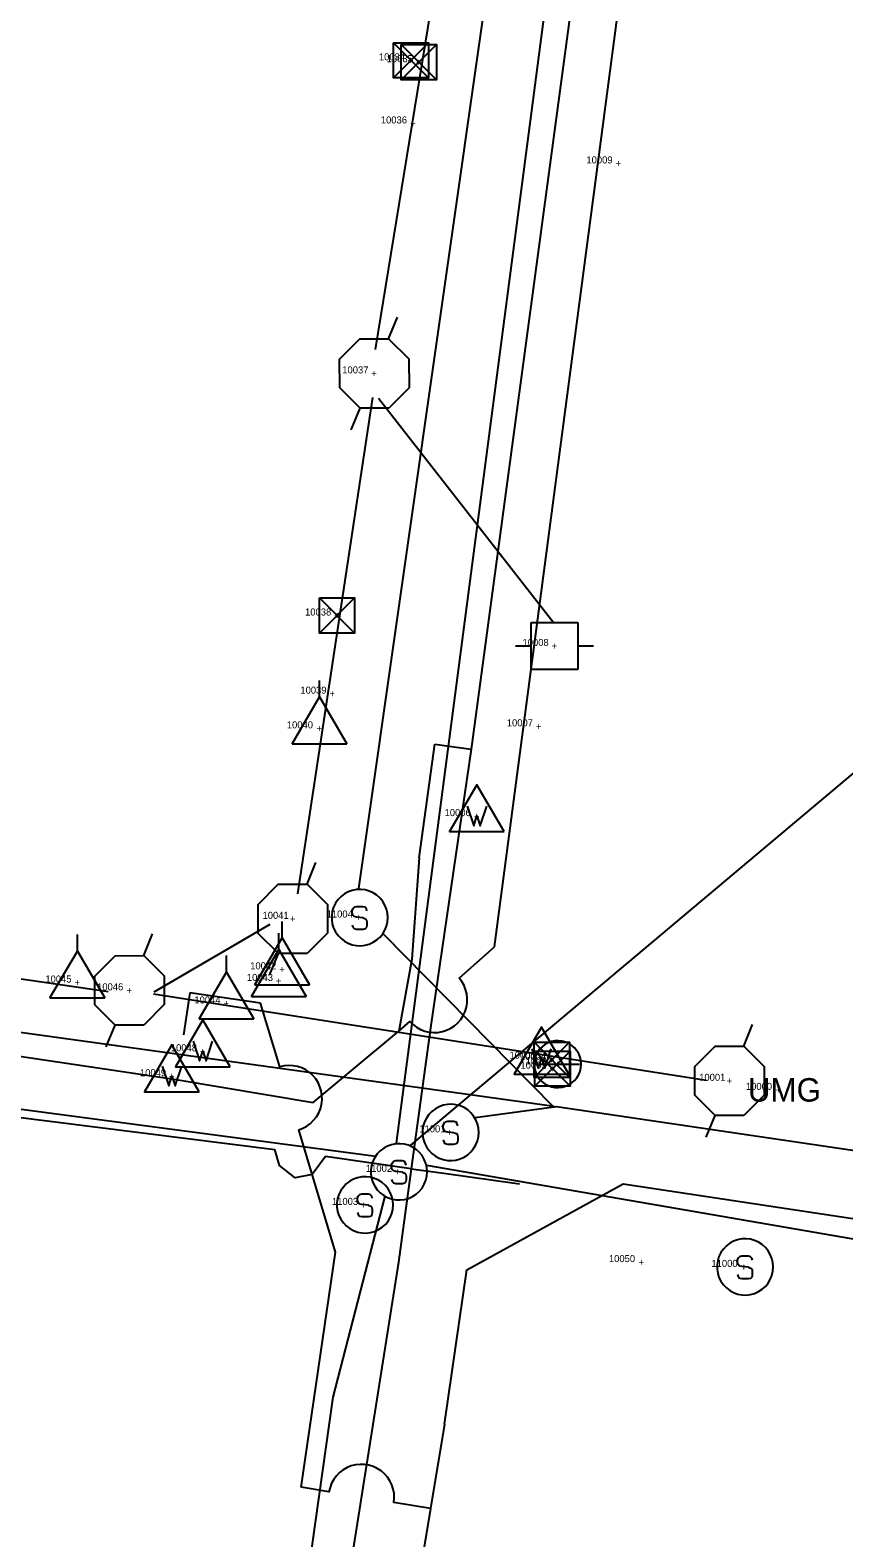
# Model space of a CAD drawing. Extents: x 1795905 to 1799611, y 243768 to 252016.
# Drawn here: x 1797403.8 to 1797577.2, y 244338.3 to 244659.6 of the extents above; entities that cross this region are included whole.
import ezdxf

# ---------------------------------------------------------------- set-up
doc = ezdxf.new("R2010")
doc.units = 0
for name, color, linetype in [('Level 50', 7, 'Continuous'), ('LS-SURVEY POINT', 7, 'Continuous'), ('OHUT', 7, 'Continuous'), ('OHUTTXT', 7, 'Continuous'), ('UGUT', 7, 'Continuous'), ('UGUTTXT', 7, 'Continuous')]:
    doc.layers.add(name, color=color, linetype=linetype)

msp = doc.modelspace()

# ---------------------------------------------------------------- linework, layer by layer
at = {"layer": 'Level 50'}
for p, q in [((1797480.17, 244593.85), (1797482.07, 244598.47)), ((1797472.19, 244574.43), (1797474.09, 244579.05)), ((1797462.79, 244477.61), (1797464.69, 244482.23)), ((1797427.98, 244462.37), (1797429.88, 244466.99)), ((1797454.8, 244458.18), (1797456.7, 244462.81)), ((1797420, 244442.94), (1797421.9, 244447.57)), ((1797555.87, 244443.09), (1797557.77, 244447.71)), ((1797547.89, 244423.67), (1797549.79, 244428.29))]:
    msp.add_line(p, q, dxfattribs=at)
for points in [[(1797480.21, 244579.07), (1797474.09, 244579.05), (1797469.75, 244583.37), (1797469.73, 244589.49), (1797474.05, 244593.83), (1797480.17, 244593.85), (1797484.51, 244589.53), (1797484.53, 244583.41)], [(1797462.83, 244462.82), (1797456.7, 244462.81), (1797452.36, 244467.12), (1797452.35, 244473.25), (1797456.66, 244477.59), (1797462.79, 244477.61), (1797467.13, 244473.29), (1797467.15, 244467.16)], [(1797428.02, 244447.58), (1797421.9, 244447.57), (1797417.56, 244451.88), (1797417.54, 244458.01), (1797421.86, 244462.35), (1797427.98, 244462.37), (1797432.32, 244458.05), (1797432.34, 244451.92)], [(1797555.91, 244428.31), (1797549.79, 244428.29), (1797545.45, 244432.61), (1797545.43, 244438.73), (1797549.75, 244443.07), (1797555.87, 244443.09), (1797560.21, 244438.77), (1797560.23, 244432.65)]]:
    msp.add_lwpolyline(points, close=True, dxfattribs=at)
at = {"layer": 'OHUT'}
for p, q in [((1797510.54, 244533.37), (1797520.54, 244533.37)), ((1797510.54, 244523.37), (1797510.54, 244533.37)), ((1797520.54, 244533.37), (1797520.54, 244523.37)), ((1797507.21, 244528.37), (1797510.54, 244528.37)), ((1797520.54, 244528.37), (1797523.88, 244528.37)), ((1797520.54, 244523.37), (1797510.54, 244523.37)), ((1797465.42, 244517.51), (1797465.42, 244521.01)), ((1797459.59, 244507.51), (1797471.26, 244507.51)), ((1797457.49, 244466.16), (1797457.49, 244469.66)), ((1797413.83, 244463.34), (1797413.83, 244466.84)), ((1797456.79, 244463.68), (1797456.79, 244467.18)), ((1797445.6, 244458.87), (1797445.6, 244462.37)), ((1797451.66, 244456.16), (1797463.33, 244456.16)), ((1797408, 244453.34), (1797419.67, 244453.34)), ((1797450.95, 244453.68), (1797462.62, 244453.68)), ((1797439.77, 244448.87), (1797451.43, 244448.87))]:
    msp.add_line(p, q, dxfattribs=at)
for points in [[(1797459.59, 244507.51), (1797465.42, 244517.51), (1797471.26, 244507.51)], [(1797451.66, 244456.16), (1797457.49, 244466.16), (1797463.33, 244456.16)], [(1797408, 244453.34), (1797413.83, 244463.34), (1797419.67, 244453.34)], [(1797450.95, 244453.68), (1797456.79, 244463.68), (1797462.62, 244453.68)], [(1797439.77, 244448.87), (1797445.6, 244458.87), (1797451.43, 244448.87)]]:
    msp.add_lwpolyline(points, dxfattribs=at)
at = {"layer": 'OHUTTXT'}
for p, q in [((1797477.37, 244591.55), (1797491.04, 244675.3)), ((1797460.84, 244475.55), (1797476.81, 244581.29)), ((1797478.02, 244581.15), (1797515.39, 244533.3)), ((1797420.39, 244454.68), (1797321.24, 244469.05)), ((1797430.21, 244454.65), (1797454.9, 244469.08)), ((1797430.09, 244454.22), (1797547.86, 244435.82))]:
    msp.add_line(p, q, dxfattribs=at)
at = {"layer": 'UGUT'}
for p, q in [((1797481.19, 244656.94), (1797488.69, 244649.44)), ((1797488.69, 244656.94), (1797481.19, 244649.44)), ((1797482.85, 244656.54), (1797490.35, 244649.04)), ((1797490.35, 244656.54), (1797482.85, 244649.04)), ((1797465.44, 244538.61), (1797472.94, 244531.11)), ((1797472.94, 244538.61), (1797465.44, 244531.11)), ((1797472.43, 244471.45), (1797472.43, 244471.9)), ((1797472.56, 244471), (1797472.43, 244471.45)), ((1797475.18, 244472.67), (1797474.67, 244472.79)), ((1797475.44, 244472.35), (1797475.18, 244472.67)), ((1797475.57, 244471.9), (1797475.44, 244472.35)), ((1797472.43, 244468.89), (1797472.56, 244468.44)), ((1797472.81, 244470.68), (1797472.56, 244471)), ((1797472.56, 244468.44), (1797472.81, 244468.12)), ((1797473.33, 244470.55), (1797472.81, 244470.68)), ((1797474.74, 244470.43), (1797473.33, 244470.55)), ((1797474.74, 244470.43), (1797475.25, 244470.23)), ((1797475.57, 244469.91), (1797475.25, 244470.23)), ((1797475.25, 244468.12), (1797475.57, 244468.44)), ((1797475.63, 244469.47), (1797475.57, 244469.91)), ((1797475.57, 244468.44), (1797475.63, 244468.89)), ((1797475.63, 244468.89), (1797475.63, 244469.47)), ((1797472.81, 244468.12), (1797473.33, 244467.99)), ((1797473.33, 244467.99), (1797474.74, 244467.99)), ((1797474.74, 244467.99), (1797475.25, 244468.12)), ((1797511.23, 244443.92), (1797518.73, 244436.42)), ((1797518.73, 244443.92), (1797511.23, 244436.42)), ((1797511.36, 244442.04), (1797518.86, 244434.54)), ((1797518.86, 244442.04), (1797511.36, 244434.54)), ((1797511.55, 244439.23), (1797520.88, 244439.23)), ((1797494.56, 244426.87), (1797494.05, 244427)), ((1797494.81, 244426.55), (1797494.56, 244426.87)), ((1797494.94, 244426.11), (1797494.81, 244426.55)), ((1797491.81, 244425.66), (1797491.81, 244426.11)), ((1797491.93, 244425.21), (1797491.81, 244425.66)), ((1797492.19, 244424.89), (1797491.93, 244425.21)), ((1797492.7, 244424.76), (1797492.19, 244424.89)), ((1797494.11, 244424.63), (1797492.7, 244424.76)), ((1797494.11, 244424.63), (1797494.62, 244424.44)), ((1797494.94, 244424.12), (1797494.62, 244424.44)), ((1797495.01, 244423.67), (1797494.94, 244424.12)), ((1797495.01, 244423.1), (1797495.01, 244423.67)), ((1797491.81, 244423.1), (1797491.93, 244422.65)), ((1797491.93, 244422.65), (1797492.19, 244422.33)), ((1797492.19, 244422.33), (1797492.7, 244422.2)), ((1797492.7, 244422.2), (1797494.11, 244422.2)), ((1797494.11, 244422.2), (1797494.62, 244422.33)), ((1797494.62, 244422.33), (1797494.94, 244422.65)), ((1797494.94, 244422.65), (1797495.01, 244423.1)), ((1797480.8, 244417.25), (1797480.8, 244417.7)), ((1797480.93, 244416.8), (1797480.8, 244417.25)), ((1797481.19, 244416.48), (1797480.93, 244416.8)), ((1797483.56, 244418.47), (1797483.04, 244418.6)), ((1797483.81, 244418.15), (1797483.56, 244418.47)), ((1797483.94, 244417.7), (1797483.81, 244418.15)), ((1797480.8, 244414.69), (1797480.93, 244414.24)), ((1797480.93, 244414.24), (1797481.19, 244413.92)), ((1797481.7, 244416.36), (1797481.19, 244416.48)), ((1797481.19, 244413.92), (1797481.7, 244413.8)), ((1797483.11, 244416.23), (1797481.7, 244416.36)), ((1797481.7, 244413.8), (1797483.11, 244413.8)), ((1797483.11, 244416.23), (1797483.62, 244416.04)), ((1797483.11, 244413.8), (1797483.62, 244413.92)), ((1797483.94, 244415.72), (1797483.62, 244416.04)), ((1797483.62, 244413.92), (1797483.94, 244414.24)), ((1797484, 244415.27), (1797483.94, 244415.72)), ((1797483.94, 244414.24), (1797484, 244414.69)), ((1797484, 244414.69), (1797484, 244415.27)), ((1797473.56, 244410.2), (1797473.56, 244410.65)), ((1797476.32, 244411.41), (1797475.8, 244411.54)), ((1797476.57, 244411.09), (1797476.32, 244411.41)), ((1797476.7, 244410.65), (1797476.57, 244411.09)), ((1797473.69, 244409.75), (1797473.56, 244410.2)), ((1797473.56, 244407.64), (1797473.69, 244407.19)), ((1797473.95, 244409.43), (1797473.69, 244409.75)), ((1797473.69, 244407.19), (1797473.95, 244406.87)), ((1797474.46, 244409.3), (1797473.95, 244409.43)), ((1797475.87, 244409.17), (1797474.46, 244409.3)), ((1797475.87, 244409.17), (1797476.38, 244408.98)), ((1797476.7, 244408.66), (1797476.38, 244408.98)), ((1797476.38, 244406.87), (1797476.7, 244407.19)), ((1797476.77, 244408.21), (1797476.7, 244408.66)), ((1797476.7, 244407.19), (1797476.77, 244407.64)), ((1797476.77, 244407.64), (1797476.77, 244408.21)), ((1797473.95, 244406.87), (1797474.46, 244406.74)), ((1797474.46, 244406.74), (1797475.87, 244406.74)), ((1797475.87, 244406.74), (1797476.38, 244406.87)), ((1797557.32, 244398.2), (1797556.81, 244398.33)), ((1797557.58, 244397.88), (1797557.32, 244398.2)), ((1797557.71, 244397.44), (1797557.58, 244397.88)), ((1797554.57, 244396.99), (1797554.57, 244397.44)), ((1797554.7, 244396.54), (1797554.57, 244396.99)), ((1797554.57, 244394.43), (1797554.7, 244393.98)), ((1797554.96, 244396.22), (1797554.7, 244396.54)), ((1797555.47, 244396.09), (1797554.96, 244396.22)), ((1797556.88, 244395.96), (1797555.47, 244396.09)), ((1797556.88, 244395.96), (1797557.39, 244395.77)), ((1797557.71, 244395.45), (1797557.39, 244395.77)), ((1797557.77, 244395), (1797557.71, 244395.45)), ((1797557.71, 244393.98), (1797557.77, 244394.43)), ((1797557.77, 244394.43), (1797557.77, 244395)), ((1797554.7, 244393.98), (1797554.96, 244393.66)), ((1797554.96, 244393.66), (1797555.47, 244393.53)), ((1797555.47, 244393.53), (1797556.88, 244393.53)), ((1797556.88, 244393.53), (1797557.39, 244393.66)), ((1797557.39, 244393.66), (1797557.71, 244393.98))]:
    msp.add_line(p, q, dxfattribs=at)
for points in [[(1797481.19, 244656.94), (1797488.69, 244656.94), (1797488.69, 244649.44), (1797481.19, 244649.44)], [(1797482.85, 244656.54), (1797490.35, 244656.54), (1797490.35, 244649.04), (1797482.85, 244649.04)], [(1797465.44, 244538.61), (1797472.94, 244538.61), (1797472.94, 244531.11), (1797465.44, 244531.11)], [(1797504.84, 244488.8), (1797499, 244498.8), (1797493.17, 244488.8)], [(1797480.02, 244470.49), (1797479.95, 244471.4), (1797479.74, 244472.3), (1797479.4, 244473.15), (1797478.93, 244473.94), (1797478.35, 244474.65), (1797477.66, 244475.26), (1797476.89, 244475.76), (1797476.05, 244476.13), (1797475.16, 244476.38), (1797474.25, 244476.48), (1797473.33, 244476.45), (1797472.43, 244476.27), (1797471.57, 244475.96), (1797470.76, 244475.52), (1797470.03, 244474.97), (1797469.39, 244474.31), (1797468.86, 244473.55), (1797468.46, 244472.73), (1797468.18, 244471.85), (1797468.04, 244470.95), (1797468.04, 244470.03), (1797468.18, 244469.12), (1797468.46, 244468.25), (1797468.86, 244467.42), (1797469.39, 244466.67), (1797470.03, 244466.01), (1797470.76, 244465.45), (1797471.57, 244465.01), (1797472.43, 244464.7), (1797473.33, 244464.53), (1797474.25, 244464.49), (1797475.16, 244464.6), (1797476.05, 244464.84), (1797476.89, 244465.22), (1797477.66, 244465.72), (1797478.35, 244466.33), (1797478.93, 244467.04), (1797479.4, 244467.83), (1797479.74, 244468.68), (1797479.95, 244469.57)], [(1797446.42, 244438.69), (1797440.59, 244448.69), (1797434.76, 244438.69)], [(1797518.6, 244437.12), (1797512.77, 244447.12), (1797506.93, 244437.12)], [(1797439.83, 244433.37), (1797434, 244443.37), (1797428.16, 244433.37)], [(1797521.21, 244439.23), (1797521.16, 244439.99), (1797520.98, 244440.73), (1797520.7, 244441.44), (1797520.3, 244442.1), (1797519.82, 244442.69), (1797519.25, 244443.2), (1797518.6, 244443.62), (1797517.9, 244443.93), (1797517.17, 244444.13), (1797516.41, 244444.22), (1797515.64, 244444.19), (1797514.89, 244444.05), (1797514.17, 244443.79), (1797513.5, 244443.42), (1797512.89, 244442.96), (1797512.36, 244442.41), (1797511.92, 244441.78), (1797511.58, 244441.09), (1797511.35, 244440.36), (1797511.23, 244439.61), (1797511.23, 244438.84), (1797511.35, 244438.09), (1797511.58, 244437.36), (1797511.92, 244436.67), (1797512.36, 244436.04), (1797512.89, 244435.49), (1797513.5, 244435.03), (1797514.17, 244434.66), (1797514.89, 244434.4), (1797515.64, 244434.26), (1797516.41, 244434.23), (1797517.17, 244434.32), (1797517.9, 244434.52), (1797518.6, 244434.83), (1797519.25, 244435.25), (1797519.82, 244435.76), (1797520.3, 244436.35), (1797520.7, 244437.01), (1797520.98, 244437.72), (1797521.16, 244438.46)], [(1797511.23, 244443.92), (1797518.73, 244443.92), (1797518.73, 244436.42), (1797511.23, 244436.42)], [(1797511.36, 244442.04), (1797518.86, 244442.04), (1797518.86, 244434.54), (1797511.36, 244434.54)], [(1797499.4, 244424.7), (1797499.33, 244425.61), (1797499.12, 244426.51), (1797498.77, 244427.36), (1797498.3, 244428.15), (1797497.72, 244428.86), (1797497.03, 244429.47), (1797496.26, 244429.97), (1797495.43, 244430.34), (1797494.54, 244430.59), (1797493.63, 244430.69), (1797492.71, 244430.66), (1797491.81, 244430.48), (1797490.94, 244430.17), (1797490.14, 244429.73), (1797489.41, 244429.18), (1797488.77, 244428.51), (1797488.24, 244427.76), (1797487.83, 244426.94), (1797487.55, 244426.06), (1797487.41, 244425.16), (1797487.41, 244424.24), (1797487.55, 244423.33), (1797487.83, 244422.45), (1797488.24, 244421.63), (1797488.77, 244420.88), (1797489.41, 244420.22), (1797490.14, 244419.66), (1797490.94, 244419.22), (1797491.81, 244418.91), (1797492.71, 244418.74), (1797493.63, 244418.7), (1797494.54, 244418.81), (1797495.43, 244419.05), (1797496.26, 244419.43), (1797497.03, 244419.93), (1797497.72, 244420.54), (1797498.3, 244421.24), (1797498.77, 244422.03), (1797499.12, 244422.89), (1797499.33, 244423.78)], [(1797488.4, 244416.29), (1797488.32, 244417.21), (1797488.12, 244418.1), (1797487.77, 244418.95), (1797487.3, 244419.74), (1797486.72, 244420.45), (1797486.03, 244421.06), (1797485.26, 244421.56), (1797484.42, 244421.94), (1797483.54, 244422.18), (1797482.62, 244422.29), (1797481.71, 244422.25), (1797480.81, 244422.08), (1797479.94, 244421.77), (1797479.13, 244421.33), (1797478.4, 244420.77), (1797477.77, 244420.11), (1797477.24, 244419.36), (1797476.83, 244418.53), (1797476.55, 244417.66), (1797476.41, 244416.75), (1797476.41, 244415.83), (1797476.55, 244414.92), (1797476.83, 244414.05), (1797477.24, 244413.23), (1797477.77, 244412.47), (1797478.4, 244411.81), (1797479.13, 244411.25), (1797479.94, 244410.82), (1797480.81, 244410.51), (1797481.71, 244410.33), (1797482.62, 244410.3), (1797483.54, 244410.4), (1797484.42, 244410.64), (1797485.26, 244411.02), (1797486.03, 244411.52), (1797486.72, 244412.13), (1797487.3, 244412.84), (1797487.77, 244413.63), (1797488.12, 244414.48), (1797488.32, 244415.37)], [(1797481.16, 244409.24), (1797481.09, 244410.15), (1797480.88, 244411.05), (1797480.53, 244411.9), (1797480.06, 244412.69), (1797479.48, 244413.4), (1797478.79, 244414.01), (1797478.02, 244414.51), (1797477.18, 244414.88), (1797476.3, 244415.13), (1797475.39, 244415.23), (1797474.47, 244415.2), (1797473.57, 244415.02), (1797472.7, 244414.71), (1797471.89, 244414.27), (1797471.16, 244413.72), (1797470.53, 244413.05), (1797470, 244412.3), (1797469.59, 244411.48), (1797469.31, 244410.6), (1797469.17, 244409.7), (1797469.17, 244408.78), (1797469.31, 244407.87), (1797469.59, 244406.99), (1797470, 244406.17), (1797470.53, 244405.42), (1797471.16, 244404.76), (1797471.89, 244404.2), (1797472.7, 244403.76), (1797473.57, 244403.45), (1797474.47, 244403.28), (1797475.39, 244403.24), (1797476.3, 244403.35), (1797477.18, 244403.59), (1797478.02, 244403.97), (1797478.79, 244404.47), (1797479.48, 244405.08), (1797480.06, 244405.78), (1797480.53, 244406.57), (1797480.88, 244407.43), (1797481.09, 244408.32)], [(1797562.16, 244396.03), (1797562.09, 244396.94), (1797561.88, 244397.84), (1797561.54, 244398.69), (1797561.07, 244399.48), (1797560.49, 244400.19), (1797559.8, 244400.8), (1797559.03, 244401.3), (1797558.19, 244401.67), (1797557.31, 244401.92), (1797556.39, 244402.02), (1797555.48, 244401.99), (1797554.57, 244401.81), (1797553.71, 244401.5), (1797552.9, 244401.06), (1797552.17, 244400.51), (1797551.53, 244399.84), (1797551.01, 244399.09), (1797550.6, 244398.27), (1797550.32, 244397.39), (1797550.18, 244396.48), (1797550.18, 244395.57), (1797550.32, 244394.66), (1797550.6, 244393.78), (1797551.01, 244392.96), (1797551.53, 244392.21), (1797552.17, 244391.55), (1797552.9, 244390.99), (1797553.71, 244390.55), (1797554.57, 244390.24), (1797555.48, 244390.07), (1797556.39, 244390.03), (1797557.31, 244390.14), (1797558.19, 244390.38), (1797559.03, 244390.76), (1797559.8, 244391.25), (1797560.49, 244391.87), (1797561.07, 244392.57), (1797561.54, 244393.36), (1797561.88, 244394.22), (1797562.09, 244395.11)]]:
    msp.add_lwpolyline(points, close=True, dxfattribs=at)
for points in [[(1797496.92, 244494.21), (1797498.31, 244490.05), (1797499, 244492.13), (1797499.7, 244490.05), (1797501.09, 244494.21)], [(1797472.43, 244471.9), (1797472.56, 244472.35), (1797472.81, 244472.67)], [(1797474.67, 244472.79), (1797473.33, 244472.79), (1797472.81, 244472.67)], [(1797438.51, 244444.11), (1797439.9, 244439.94), (1797440.59, 244442.03), (1797441.28, 244439.94), (1797442.67, 244444.11)], [(1797510.68, 244442.54), (1797512.07, 244438.37), (1797512.77, 244440.46), (1797513.46, 244438.37), (1797514.85, 244442.54)], [(1797431.91, 244438.79), (1797433.3, 244434.62), (1797434, 244436.71), (1797434.69, 244434.62), (1797436.08, 244438.79)], [(1797491.81, 244426.11), (1797491.93, 244426.55), (1797492.19, 244426.87)], [(1797494.05, 244427), (1797492.7, 244427), (1797492.19, 244426.87)], [(1797480.8, 244417.7), (1797480.93, 244418.15), (1797481.19, 244418.47)], [(1797483.04, 244418.6), (1797481.7, 244418.6), (1797481.19, 244418.47)], [(1797473.56, 244410.65), (1797473.69, 244411.09), (1797473.95, 244411.41)], [(1797475.8, 244411.54), (1797474.46, 244411.54), (1797473.95, 244411.41)], [(1797554.57, 244397.44), (1797554.7, 244397.88), (1797554.96, 244398.2)], [(1797556.81, 244398.33), (1797555.47, 244398.33), (1797554.96, 244398.2)]]:
    msp.add_lwpolyline(points, dxfattribs=at)
at = {"layer": 'UGUTTXT'}
for p, q in [((1797473.84, 244476.69), (1797534.35, 244900.9)), ((1797481.84, 244422.43), (1797527.52, 244770.8)), ((1797484.89, 244421.99), (1797742.46, 244638.3)), ((1797515.47, 244430.24), (1796818.57, 244526.55)), ((1797477.44, 244419.55), (1796815.46, 244507.3)), ((1797515.32, 244430.14), (1797479.19, 244466.86)), ((1797488.24, 244417.74), (1797734.68, 244375.07))]:
    msp.add_line(p, q, dxfattribs=at)
for points in [[(1797531.25, 244754.88), (1797497.75, 244506.39)], [(1797502.73, 244464.27), (1797530.89, 244677.28)], [(1797486.7, 244483.23), (1797490.01, 244507.45)], [(1797490.01, 244507.45), (1797497.75, 244506.39)], [(1797497.75, 244506.39), (1797489.19, 244447.46)], [(1797080.39, 244488.73), (1797434.86, 244436)], [(1797486.7, 244483.23), (1797485.15, 244461.64)], [(1797482.33, 244446.24), (1797484.7, 244448.34), (1797485.38, 244447.67), (1797486.14, 244447.09), (1797486.98, 244446.63), (1797487.87, 244446.29), (1797488.8, 244446.07), (1797489.75, 244445.98), (1797490.7, 244446.02), (1797491.64, 244446.18), (1797492.55, 244446.48), (1797493.41, 244446.89), (1797494.21, 244447.42), (1797494.92, 244448.06), (1797495.55, 244448.78), (1797496.06, 244449.58), (1797496.47, 244450.45), (1797496.75, 244451.36), (1797496.91, 244452.3), (1797496.94, 244453.26), (1797496.83, 244454.2), (1797496.6, 244455.13), (1797496.25, 244456.02), (1797495.77, 244456.85), (1797495.19, 244457.6), (1797502.73, 244464.27)], [(1797485.15, 244461.64), (1797482.33, 244446.24)], [(1797437.78, 244454.42), (1797436.45, 244445.47)], [(1797452.89, 244452.26), (1797437.78, 244454.42)], [(1797468.86, 244399.16), (1797461.01, 244425.26), (1797461.9, 244425.6), (1797462.74, 244426.05), (1797463.51, 244426.62), (1797464.2, 244427.28), (1797464.79, 244428.03), (1797465.27, 244428.86), (1797465.63, 244429.74), (1797465.87, 244430.67), (1797465.98, 244431.62), (1797465.97, 244432.57), (1797465.82, 244433.52), (1797465.54, 244434.43), (1797465.15, 244435.3), (1797464.63, 244436.11), (1797464.02, 244436.84), (1797463.31, 244437.47), (1797462.52, 244438.01), (1797461.66, 244438.43), (1797460.75, 244438.74), (1797459.81, 244438.91), (1797458.86, 244438.96), (1797457.91, 244438.88), (1797456.98, 244438.66), (1797452.89, 244452.26)], [(1797472.19, 244437.81), (1797482.33, 244446.24)], [(1797489.19, 244447.46), (1797485.02, 244416.96)], [(1797295.03, 244441.29), (1797455.94, 244421.06)], [(1797464.11, 244431.1), (1797472.19, 244437.81)], [(1797434.86, 244436), (1797464.11, 244431.1)], [(1797498.61, 244427.9), (1797515.93, 244430.25), (1797774.59, 244392.08)], [(1797485.02, 244416.96), (1797466.72, 244419.54), (1797463.88, 244415.7), (1797460.26, 244414.99), (1797456.89, 244417.61), (1797455.94, 244421.06)], [(1797485.02, 244416.96), (1797482.29, 244397.02)], [(1797485.02, 244416.96), (1797491.95, 244415.98), (1797508.11, 244413.7)], [(1797496.82, 244395.41), (1797530.17, 244413.7)], [(1797530.17, 244413.7), (1797675.55, 244391.81)], [(1797479.4, 244411.11), (1797468.31, 244368.23), (1797421.64, 244037.11)], [(1797461.52, 244349.07), (1797468.86, 244399.16)], [(1797482.29, 244397.02), (1797449.63, 244190.44), (1797426.69, 244039.28)], [(1797492.06, 244362.52), (1797496.82, 244395.41)], [(1797492.06, 244362.52), (1797489.08, 244344.51)], [(1797489.08, 244344.51), (1797481.28, 244345.8), (1797481.37, 244346.75), (1797481.33, 244347.71), (1797481.17, 244348.65), (1797480.87, 244349.56), (1797480.46, 244350.42), (1797479.93, 244351.21), (1797479.29, 244351.93), (1797478.57, 244352.55), (1797477.77, 244353.07), (1797476.9, 244353.48), (1797475.99, 244353.76), (1797475.04, 244353.92), (1797474.09, 244353.94), (1797473.14, 244353.84), (1797472.21, 244353.61), (1797471.32, 244353.25), (1797470.49, 244352.78), (1797469.74, 244352.19), (1797469.07, 244351.51), (1797468.49, 244350.75), (1797468.03, 244349.91), (1797467.69, 244349.02), (1797467.47, 244348.09), (1797461.52, 244349.07)], [(1797489.08, 244344.51), (1797457.9, 244156.26)]]:
    msp.add_lwpolyline(points, dxfattribs=at)

# ---------------------------------------------------------------- texts
at = {"layer": 'LS-SURVEY POINT'}
for s, p in [('10034', (1797478.11, 244653.19)), ('10035', (1797479.77, 244652.79)), ('+', (1797484.31, 244652.44)), ('+', (1797485.98, 244652.04)), ('10036', (1797478.52, 244639.73)), ('+', (1797484.8, 244638.98)), ('10009', (1797522.34, 244631.21)), ('+', (1797528.54, 244630.46)), ('10037', (1797470.3, 244586.45)), ('+', (1797476.5, 244585.7)), ('10038', (1797462.37, 244534.86)), ('+', (1797468.57, 244534.11)), ('10008', (1797508.72, 244528.37)), ('+', (1797514.92, 244527.62)), ('10039', (1797461.37, 244518.2)), ('+', (1797467.57, 244517.45)), ('10040', (1797458.48, 244510.81)), ('+', (1797464.8, 244510.06)), ('10007', (1797505.37, 244511.25)), ('+', (1797511.57, 244510.5)), ('10006', (1797492.11, 244492.1)), ('+', (1797498.38, 244491.35)), ('10041', (1797453.3, 244470.21)), ('11004', (1797466.97, 244470.49)), ('+', (1797459.12, 244469.46)), ('+', (1797473.17, 244469.74)), ('10042', (1797450.67, 244459.46)), ('+', (1797456.87, 244458.71)), ('10045', (1797407.01, 244456.64)), ('+', (1797413.21, 244455.89)), ('10046', (1797418.04, 244454.97)), ('+', (1797424.32, 244454.22)), ('10043', (1797449.96, 244456.98)), ('+', (1797456.16, 244456.23)), ('10044', (1797438.77, 244452.17)), ('+', (1797444.97, 244451.42)), ('10048', (1797433.76, 244441.99)), ('+', (1797439.96, 244441.24)), ('10005', (1797505.94, 244440.42)), ('10004', (1797508.16, 244440.17)), ('10003', (1797508.28, 244438.29)), ('10002', (1797509.39, 244439.23)), ('+', (1797512.14, 244439.67)), ('+', (1797514.36, 244439.42)), ('+', (1797515.59, 244438.48)), ('10049', (1797427.17, 244436.67)), ('+', (1797433.37, 244435.92)), ('+', (1797514.48, 244437.54)), ('10001', (1797546.38, 244435.69)), ('+', (1797552.2, 244434.94)), ('10000', (1797556.34, 244433.76)), ('+', (1797562.66, 244433.01)), ('11001', (1797486.72, 244424.7)), ('+', (1797492.54, 244423.95)), ('11002', (1797475.34, 244416.29)), ('+', (1797481.54, 244415.54)), ('11003', (1797468.1, 244409.24)), ('+', (1797474.3, 244408.49)), ('10050', (1797527.14, 244397.05)), ('+', (1797533.46, 244396.3)), ('11000', (1797548.99, 244396.03)), ('+', (1797555.31, 244395.28))]:
    msp.add_text(s, height=1.5, dxfattribs=at).set_placement(p)
at = {"layer": 'UGUT'}
for p in [(1797484.51, 244652.69), (1797486.17, 244652.29), (1797468.77, 244534.36), (1797514.55, 244439.67), (1797514.68, 244437.79)]:
    msp.add_text('+', height=1, rotation=360, dxfattribs=at).set_placement(p)
for s, height, p in [('UMG', 5, (1797556.75, 244431.26)), ('+', 0.1, (1797563.24, 244433.71))]:
    msp.add_text(s, height=height, dxfattribs=at).set_placement(p)

doc.saveas('drawing.dxf')
